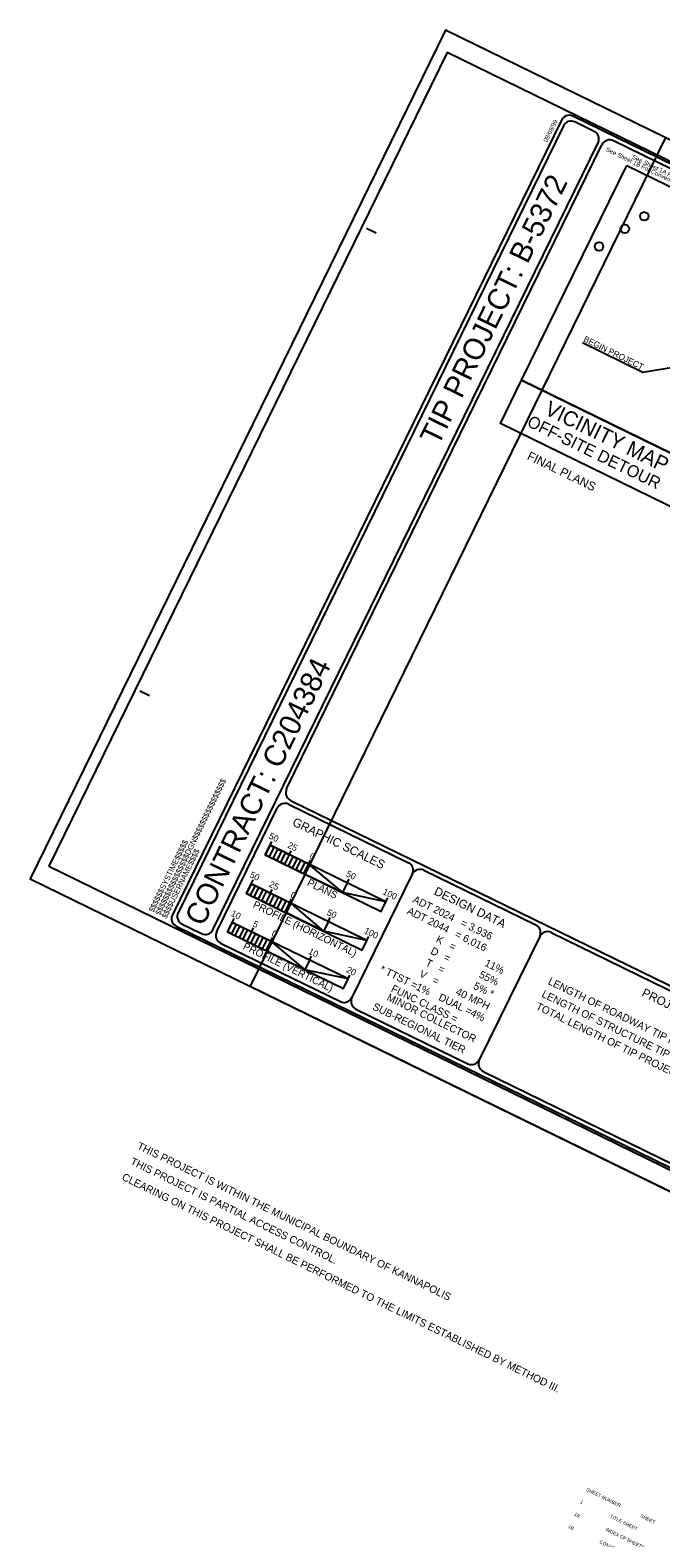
# Model space of a CAD drawing. Extents: x 1517888 to 1526099, y 633375 to 640181.
# Drawn here: x 1517888 to 1519355, y 636669 to 640181 of the extents above; entities that cross this region are included whole.
import ezdxf

# ---------------------------------------------------------------- set-up
doc = ezdxf.new("R2010")
doc.units = 0
for name, color, linetype in [('Default', 7, 'Continuous'), ('Sheet Cutting Line CELL', 7, 'Continuous'), ('Sheet Data Field CELL', 7, 'Continuous'), ('Sheet Data Text CELL', 7, 'Continuous'), ('Sheet Plot Border Inside CELL', 7, 'Continuous'), ('Sheet Plot Border Outside CELL', 7, 'Continuous'), ('Sheet Title CELL', 7, 'Continuous')]:
    doc.layers.add(name, color=color, linetype=linetype)

msp = doc.modelspace()

# ---------------------------------------------------------------- linework, layer by layer
at = {"layer": 'Sheet Cutting Line CELL'}
for p, q in [((1519366.5, 639930.5), (1518399.9, 637954.2)), ((1518399.9, 637954.2), (1521425.5, 636474.5))]:
    msp.add_line(p, q, dxfattribs=at)
at = {"layer": 'Sheet Data Field CELL'}
for p, q in [((1519172.9, 639453.3), (1519313.6, 639384.5)), ((1519313.6, 639384.5), (1519393.4, 639397.1)), ((1518446.1, 638282.5), (1518450.4, 638291.5)), ((1518491, 638260.5), (1518495.4, 638269.5)), ((1518625.7, 638194.7), (1518630.1, 638203.6)), ((1518715.5, 638150.7), (1518719.9, 638159.7)), ((1518210.1, 638102.7), (1518210.1, 638102.7))]:
    msp.add_line(p, q, dxfattribs=at)
for points in [[(1519276.2, 639865.9), (1519871, 639575), (1519626.2, 639074.5), (1519031.4, 639365.4)], [(1519031.4, 639365.4), (1519626.2, 639074.5), (1519577, 638973.7), (1518982.1, 639264.6)]]:
    msp.add_lwpolyline(points, close=True, dxfattribs=at)
for centre in [(1519316.9, 639747.3), (1519271.6, 639718.1), (1519211.5, 639676.9)]:
    msp.add_circle(centre, 10, dxfattribs=at)
at = {"layer": 'Sheet Plot Border Inside CELL'}
msp.add_lwpolyline([(1517931.1, 638233.4), (1520925.2, 636769.1), (1521852.3, 638664.7), (1518858.2, 640129.1)], close=True, dxfattribs=at)
at = {"layer": 'Sheet Plot Border Outside CELL'}
msp.add_lwpolyline([(1521880.1, 638701.1), (1518854.6, 640180.8), (1517888, 638204.5), (1520913.6, 636724.8)], close=True, dxfattribs=at)
at = {"layer": 'Sheet Title CELL'}
for p, q in [((1518313, 638085.7), (1519209.3, 639918.3)), ((1518484.6, 638413.7), (1519218.3, 639913.9)), ((1518670.3, 639719.9), (1518692.8, 639708.9)), ((1518670.3, 639719.9), (1518692.8, 639708.9)), ((1518143.1, 638641.9), (1518165.6, 638631)), ((1518143.1, 638641.9), (1518165.6, 638631)), ((1518493.8, 638387), (1521045, 637139.2)), ((1518322, 638081.3), (1518462.6, 638368.8)), ((1518489.4, 638378), (1518767.9, 638241.8)), ((1518446, 638282.5), (1518435, 638260.1)), ((1518446, 638282.5), (1518450.4, 638291.5)), ((1518446, 638282.5), (1518446, 638282.5)), ((1518715.5, 638150.7), (1518446, 638282.5)), ((1518450.4, 638291.5), (1518450.4, 638291.5)), ((1518435, 638260.1), (1518704.5, 638128.2)), ((1518490.9, 638260.5), (1518495.3, 638269.5)), ((1518508.9, 638251.8), (1518497.9, 638229.3)), ((1518535.8, 638238.6), (1518540.2, 638247.5)), ((1518777, 638215), (1518636.4, 637927.5)), ((1518803.8, 638224.2), (1519064.3, 638096.8)), ((1518402.1, 638192.7), (1518391.1, 638170.2)), ((1518402.1, 638192.7), (1518406.5, 638201.7)), ((1518402.1, 638192.7), (1518406.5, 638201.7)), ((1518402.1, 638192.7), (1518402.1, 638192.7)), ((1518671.6, 638060.9), (1518402.1, 638192.7)), ((1518402.1, 638192.7), (1518402.1, 638192.7)), ((1518671.6, 638060.9), (1518402.1, 638192.7)), ((1518406.5, 638201.7), (1518406.5, 638201.7)), ((1518447, 638170.7), (1518451.4, 638179.7)), ((1518447, 638170.7), (1518451.4, 638179.7)), ((1518625.7, 638194.6), (1518614.7, 638172.2)), ((1518625.7, 638194.6), (1518630.1, 638203.6)), ((1518391.1, 638170.2), (1518660.6, 638038.4)), ((1518465, 638161.9), (1518454, 638139.5)), ((1518491.9, 638148.8), (1518496.3, 638157.7)), ((1518491.9, 638148.8), (1518496.3, 638157.7)), ((1518704.5, 638128.2), (1518715.5, 638150.7)), ((1518715.5, 638150.7), (1518719.9, 638159.7)), ((1518210, 638102.7), (1518210, 638102.7)), ((1518210, 638102.7), (1518210, 638102.7)), ((1518210, 638102.7), (1518210, 638102.7)), ((1518210, 638102.7), (1518210, 638102.7)), ((1518358.2, 638102.8), (1518347.2, 638080.4)), ((1518358.2, 638102.8), (1518362.5, 638111.8)), ((1518358.2, 638102.8), (1518362.5, 638111.8)), ((1518358.2, 638102.8), (1518362.5, 638111.8)), ((1518358.2, 638102.8), (1518358.2, 638102.8)), ((1518627.6, 637971.1), (1518358.2, 638102.8)), ((1518358.2, 638102.8), (1518358.2, 638102.8)), ((1518627.6, 637971.1), (1518358.2, 638102.8)), ((1518358.2, 638102.8), (1518358.2, 638102.8)), ((1518627.6, 637971.1), (1518358.2, 638102.8)), ((1518362.5, 638111.8), (1518362.5, 638111.8)), ((1518581.8, 638104.8), (1518570.8, 638082.4)), ((1518581.8, 638104.8), (1518586.1, 638113.8)), ((1518581.8, 638104.8), (1518586.1, 638113.8)), ((1518347.2, 638080.4), (1518616.7, 637948.6)), ((1518403.1, 638080.9), (1518407.5, 638089.8)), ((1518403.1, 638080.9), (1518407.5, 638089.8)), ((1518403.1, 638080.9), (1518407.5, 638089.8)), ((1518421, 638072.1), (1518410, 638049.6)), ((1518448, 638058.9), (1518452.4, 638067.9)), ((1518448, 638058.9), (1518452.4, 638067.9)), ((1518448, 638058.9), (1518452.4, 638067.9)), ((1518671.6, 638060.9), (1518676, 638069.9)), ((1518671.6, 638060.9), (1518676, 638069.9)), ((1519073.5, 638070), (1518932.9, 637782.6)), ((1519100.2, 638079.2), (1519782.9, 637745.3)), ((1518660.6, 638038.4), (1518671.6, 638060.9)), ((1518537.8, 638015), (1518526.8, 637992.5)), ((1518537.8, 638015), (1518542.2, 638024)), ((1518537.8, 638015), (1518542.2, 638024)), ((1518537.8, 638015), (1518542.2, 638024)), ((1518616.7, 637948.6), (1518627.6, 637971.1)), ((1518627.6, 637971.1), (1518632, 637980)), ((1518627.6, 637971.1), (1518632, 637980)), ((1518627.6, 637971.1), (1518632, 637980))]:
    msp.add_line(p, q, dxfattribs=at)
for points in [[(1519123.9, 639971.2), (1518218.8, 638120.7)], [(1519123.9, 639971.2), (1518218.8, 638120.7)], [(1521809.7, 638679.9), (1519150.6, 639980.4)], [(1519200.1, 639945), (1519155.2, 639967)], [(1519128.5, 639957.8), (1518232.2, 638125.3)], [(1521796.3, 638675.3), (1519245.1, 639923.1)], [(1518228, 638093.9), (1520887, 636793.4)], [(1518241.4, 638098.5), (1518286.3, 638076.6)], [(1518331.2, 638054.6), (1518609.7, 637918.4)], [(1518645.6, 637900.8), (1518906.1, 637773.4)], [(1518942.1, 637755.8), (1519624.8, 637421.9)]]:
    msp.add_lwpolyline(points, dxfattribs=at)
for points in [[(1518446, 638282.5), (1518455, 638278.1), (1518444, 638255.7), (1518435, 638260.1)], [(1518464, 638273.7), (1518473, 638269.3), (1518462, 638246.9), (1518453, 638251.2)], [(1518481.9, 638264.9), (1518490.9, 638260.5), (1518480, 638238.1), (1518471, 638242.5)], [(1518499.9, 638256.1), (1518508.9, 638251.8), (1518497.9, 638229.3), (1518488.9, 638233.7)], [(1518517.9, 638247.4), (1518526.9, 638243), (1518515.9, 638220.5), (1518506.9, 638224.9)], [(1518535.8, 638238.6), (1518614.7, 638172.2), (1518524.9, 638216.1)], [(1518402.1, 638192.7), (1518411.1, 638188.3), (1518400.1, 638165.8), (1518391.1, 638170.2)], [(1518420.1, 638183.9), (1518429, 638179.5), (1518418.1, 638157), (1518409.1, 638161.4)], [(1518438, 638175.1), (1518447, 638170.7), (1518436, 638148.3), (1518427, 638152.6)], [(1518715.5, 638150.7), (1518614.7, 638172.2), (1518704.5, 638128.2)], [(1518456, 638166.3), (1518465, 638161.9), (1518454, 638139.5), (1518445, 638143.9)], [(1518474, 638157.5), (1518482.9, 638153.1), (1518472, 638130.7), (1518463, 638135.1)], [(1518491.9, 638148.8), (1518570.8, 638082.4), (1518480.9, 638126.3)], [(1518358.2, 638102.8), (1518367.1, 638098.4), (1518356.1, 638076), (1518347.2, 638080.4)], [(1518376.1, 638094.1), (1518385.1, 638089.7), (1518374.1, 638067.2), (1518365.1, 638071.6)], [(1518394.1, 638085.3), (1518403.1, 638080.9), (1518392.1, 638058.4), (1518383.1, 638062.8)], [(1518412.1, 638076.5), (1518421, 638072.1), (1518410, 638049.6), (1518401.1, 638054)], [(1518430, 638067.7), (1518439, 638063.3), (1518428, 638040.9), (1518419, 638045.2)], [(1518671.6, 638060.9), (1518570.8, 638082.4), (1518660.6, 638038.4)], [(1518448, 638058.9), (1518526.8, 637992.5), (1518437, 638036.5)], [(1518627.6, 637971.1), (1518526.8, 637992.5), (1518616.7, 637948.6)]]:
    msp.add_lwpolyline(points, close=True, dxfattribs=at)
for centre, start, end in [((1519141.9, 639962.5), 63.9377, 153.9377), ((1519146.5, 639949.1), 63.9377, 153.9377), ((1519191.4, 639927.2), 333.9377, 63.9377), ((1519236.3, 639905.2), 63.9377, 153.9377), ((1518502.6, 638405), 153.9377, 243.9377), ((1518480.6, 638360.1), 63.9377, 153.9377), ((1518759.1, 638223.9), 333.9377, 63.9377), ((1518795, 638206.3), 63.9377, 153.9377), ((1518236.8, 638112), 153.9377, 243.9377), ((1518250.2, 638116.6), 153.9377, 243.9377), ((1518295.1, 638094.6), 243.9377, 333.9377), ((1518340, 638072.6), 153.9377, 243.9377), ((1519055.6, 638078.9), 333.9377, 63.9377), ((1519091.5, 638061.3), 63.9377, 153.9377), ((1518618.5, 637936.4), 243.9377, 333.9377), ((1518654.5, 637918.9), 153.9377, 243.9377), ((1518915, 637791.4), 243.9377, 333.9377), ((1518950.9, 637773.9), 153.9377, 243.9377)]:
    msp.add_arc(centre, 20, start, end, dxfattribs=at)

# ---------------------------------------------------------------- texts
at = {"layer": 'Default'}
msp.add_text('BEGIN PROJECT', height=14.158, rotation=333.6582, dxfattribs=at).set_placement((1519173.9, 639456.8))
at = {"layer": 'Sheet Data Field CELL'}
for s, height, p in [('VICINITY MAP (N.T.S.)', 35, (1519082.4, 639287.3)), ('OFF-SITE DETOUR', 28, (1519041.9, 639259.8)), ('FINAL PLANS', 20.23, (1519042.5, 639182.3)), ('ADT 2044', 17.5, (1518763.3, 638123.6)), ('ADT 2024', 17.5, (1518776.3, 638150.4)), ('= 3,936', 17.5, (1518887.7, 638096)), ('K', 17.5, (1518830.4, 638057.6)), ('= 6,016', 17.5, (1518874.5, 638069.1)), ('D', 17.5, (1518818, 638030.5)), ('=', 17.5, (1518861.5, 638042.4)), ('* TTST =1%', 17.5, (1518699.2, 637988)), ('T', 17.5, (1518806.1, 638003.1)), ('=', 17.5, (1518835.4, 637989.2)), ('=', 17.5, (1518848.3, 638015.5)), ('11%', 17.5, (1518943.7, 638002.3)), ('V', 17.5, (1518791.7, 637977)), ('=', 17.5, (1518822.3, 637962.3)), ('5% *', 17.5, (1518917.6, 637949)), ('55%', 17.5, (1518930.5, 637975.4)), ('LENGTH OF ROADWAY TIP PROJECT B-5372 = 0.191 MILES', 17.5, (1519091.2, 637959.7)), ('MINOR COLLECTOR', 17.5, (1518716.1, 637922.1)), ('FUNC CLASS =', 17.5, (1518726.1, 637942.7)), ('DUAL =4%', 17.5, (1518836.4, 637922.5)), ('40 MPH', 17.5, (1518876.4, 637935.5)), ('LENGTH OF STRUCTURE TIP PROJECT B-5372 = 0.033 MILES', 17.5, (1519076.6, 637930.1)), ('SUB-REGIONAL TIER', 17.5, (1518683, 637900.7)), ('TOTAL LENGTH OF TIP PROJECT B-5372 =   0.224 MILES', 17.5, (1519063, 637901.2)), ('THIS PROJECT IS WITHIN THE MUNICIPAL BOUNDARY OF KANNAPOLIS', 17.5, (1518135.3, 637576.3)), ('THIS PROJECT IS PARTIAL ACCESS CONTROL.', 17.5, (1518119.6, 637540.2)), ('CLEARING ON THIS PROJECT SHALL BE PERFORMED TO THE LIMITS ESTABLISHED BY METHOD III.', 17.5, (1518099.7, 637503.9))]:
    msp.add_text(s, height=height, rotation=333.9377, dxfattribs=at).set_placement(p)
at = {"layer": 'Sheet Data Text CELL'}
for s, p in [('SHEET NUMBER                 SHEET   ', (1519181, 636779.1)), ('1                       TITLE SHEET', (1519166.9, 636750.4)), ('1B                      CONVENTIONAL SYMBOLS ', (1519138.8, 636692.9)), ('1A                      INDEX OF SHEETS, GENERAL NOTES, AND STANDARD DRAWINGS', (1519152.9, 636721.7))]:
    msp.add_text(s, height=8, rotation=333.9377, dxfattribs=at).set_placement(p)
at = {"layer": 'Sheet Title CELL'}
for s, height, rotation, p in [('09/08/99', 10.5, 63.9377, (1519090.9, 639918.6)), ('            See Sheet 1B For Conventional Plan Sheet Symbols', 10.241, 333.9377, (1519184.3, 639920.3)), ('  See Sheet 1A For Index of Sheets', 10.241, 333.9377, (1519280.3, 639885.5)), ('TIP PROJECT: B-5372', 50, 63.9377, (1518837.8, 639210.5)), ('CONTRACT: C204384', 50, 63.9377, (1518290.4, 638091.2)), ('$$$$$$$$$$$$$$$$DGN$$$$$$$$$$$$$$$$', 13.125, 63.9377, (1518190.3, 638118)), ('50', 15, 333.9377, (1518441.6, 638299)), ('GRAPHIC SCALES', 19.999, 333.9377, (1518496.4, 638329.6)), ('$$$$$$SYSTIME$$$$$', 13.125, 63.9377, (1518174.8, 638125)), ('25', 15, 333.9377, (1518485.4, 638277.5)), ('$$$$USERNAME$$$$', 13.125, 63.9377, (1518204.9, 638110.4)), ('0', 15, 333.9377, (1518536.3, 638252)), ('50', 15, 333.9377, (1518397.2, 638208.8)), ('50', 15, 333.9377, (1518621.4, 638211)), ('25', 15, 333.9377, (1518442.1, 638186.8)), ('0', 15, 333.9377, (1518492.3, 638161.9)), ('0', 15, 333.9377, (1518492.4, 638162.2)), ('PLANS', 17, 333.9377, (1518530.9, 638189.8)), ('100', 15, 333.9377, (1518706.8, 638169.3)), ('DESIGN DATA', 19.999, 333.9377, (1518825.9, 638168.5)), ('PROFILE (HORIZONTAL)', 16.999, 333.9377, (1518404.7, 638138.7)), ('10', 15, 333.9377, (1518353.6, 638118.8)), ('5', 15, 333.9377, (1518404.1, 638094.1)), ('50', 15, 333.9377, (1518576.5, 638121.1)), ('0', 15, 333.9377, (1518448.3, 638072.1)), ('0', 15, 333.9377, (1518448.3, 638072.1)), ('0', 15, 333.9377, (1518448.4, 638072.4)), ('100', 15, 333.9377, (1518663.5, 638078.5)), ('PROFILE (VERTICAL)', 16.999, 333.9377, (1518381.5, 638041.5)), ('10', 15, 333.9377, (1518533.9, 638030.6)), ('20', 15, 333.9377, (1518621.9, 637987.5)), ('PROJECT LENGTH', 19.999, 333.9377, (1519309.1, 637932.2))]:
    msp.add_text(s, height=height, rotation=rotation, dxfattribs=at).set_placement(p)

doc.saveas('drawing.dxf')
